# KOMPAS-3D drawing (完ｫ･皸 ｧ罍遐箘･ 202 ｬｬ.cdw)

Referenced files in D:\Чертежи\: Колесо зубчатое.cdw
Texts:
  Колесо зубчатое
  Сазанова Т,И.
  Текст на чертеже
  Размерные надписи
  Шероховатость
  Линия-выноска #1
  Линия-выноска #2
  Линия-выноска #3
  Отклонения формы и база
  Заголовок таблицы
  Ячейка таблицы
  Стрелка вида
  Обозначение изменения
  Фигурная скобка
  Номер узла
  Марка координационной оси
  VRCB
  Выносная надпись
  Обозначение узла
  Марка/позиционное обозначение с линией-выноской
  Марка/позиционное обозначение на линии
  Марка/позиционное обозначение без линии-выноски
  Ra 2,0
  Ra 1,6
  Ra 3,2
  Угол наклона зуба
  Js9
  Модуль
  Число зубьев
  Исходный контур
  ГОСТ 13755-81
  Степень точности по ГОСТ 1643-81
  Делительный диаметр
  1.HВ 230-260. Зубья цементировать h 0,7...0,9 мм
  2. Неуказанные  радиусы 1 мм max
  3. Штамповочные уклоны 2  min
  4.H14 ; h14 ;  IT14 2
  Сталь 40Х  ГОСТ 4543-71
Dimensions and other numbers on the sheet: 7; 48; 76; 183; 202; 30; 60; 1,25; 2 фаски; 37,5; 0,05; 0,008; 8; 3; 2; 14; 51,8; 1; 9-C; 200; 1:1; 0; 4; 5; 6; 9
